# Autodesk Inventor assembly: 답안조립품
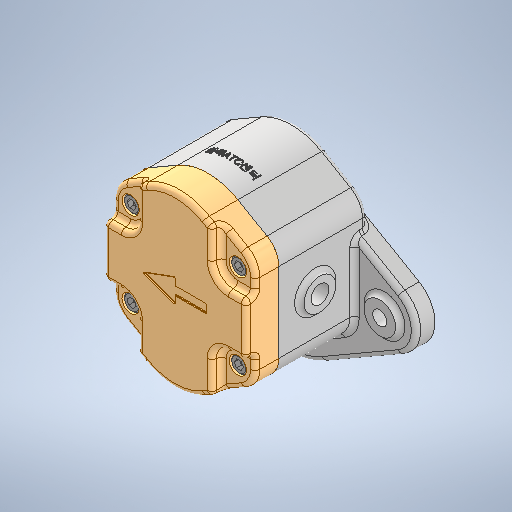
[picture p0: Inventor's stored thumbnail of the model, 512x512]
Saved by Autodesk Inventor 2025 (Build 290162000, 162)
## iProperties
Created: 2026-09
Part Number: 답안조립품
Document SubType Name: Assembly
Designer: KDI
Author: KDI
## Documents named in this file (11)
- C:\Users\KDI\Desktop\660903V1004\답안조립품.iam
- C:\Users\KDI\Desktop\660903V1004\본체\본체.ipt
- C:\Users\KDI\Desktop\660903V1004\DU 부시\DU 부시.ipt
- C:\Users\KDI\Desktop\660903V1004\스퍼기어\스퍼기어.ipt
- C:\Users\KDI\Desktop\660903V1004\구동기어\구동기어.ipt
- C:\Users\KDI\Desktop\660903V1004\오일 실 16 30 7\오일 실 16 30 7.ipt
- C:\Users\KDI\Desktop\660903V1004\가이드 블록\가이드 블록.ipt
- C:\Users\KDI\Desktop\660903V1004\3자 실링\3자 실링.ipt
- C:\Users\KDI\Desktop\660903V1004\커버\커버.ipt
- C:\Users\KDI\Desktop\660903V1004\실링\실링.ipt
- C:\Users\KDI\Desktop\660903V1004\6각 구멍붙이 볼트 M6x16\6각 구멍붙이 볼트 M6x16.ipt
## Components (11 placed, 5 different names)
1. DU 부시:1
2. DU 부시:2
3. DU 부시:3
4. DU 부시:4
5. 구동기어:1
6. 가이드 블록:1
7. 3자 실링:1
8. 6각 구멍붙이 볼트 M6x16:3
9. 6각 구멍붙이 볼트 M6x16:4
10. 6각 구멍붙이 볼트 M6x16:5
11. 6각 구멍붙이 볼트 M6x16:6
